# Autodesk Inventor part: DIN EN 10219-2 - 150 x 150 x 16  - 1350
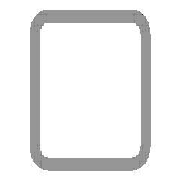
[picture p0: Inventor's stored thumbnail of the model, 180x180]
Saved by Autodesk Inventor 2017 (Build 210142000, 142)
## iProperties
_CCFamilyMember: 76
_CCFamilyDisplayName: DIN EN 10219-2 (Square Hollow Section - Cold Formed) - Cold formed welded structural hollow sections of non-alloy and fine grain structural steel
_FrameMemberDoc: Frame Member File
_Version: 15.0.0
_GetPNFromCC: 1
Created: 2017-11
Part Number: DIN EN 10219-2 - 150 x 150 x 16  - 1350
Material: Steel, Mild
Description: Cold formed welded structural hollow sections of non-alloy and fine grain structural steel
Document SubType Name: Modeling
Standard: DIN
Designer: iusti
Standard Revision: 2006-07
Standards Organization: DIN
Language: en-US
Size Designation: 150 x 150 x 16
Categories: <MemberInstance><Categories><Category DisplayName="Structural Shapes" InternalName="089c4875-fa83-4c05-b084-43b9cc11f5ed" Mnemonic="GRDR"><CategoryParameter Dis
Stock Number: 150 x 150 x 16
Mass: 79240 g
Surface Area: 12767.4 cm^2
Volume: 10094.3 cm^3
Density: 7.85 g/cm^3
Appearance: Semi-Polished
IsCustomPart: 1
G_L: 1350.000 mm
G_W: 150.000 mm
G_H: 150.000 mm
+25324788-8590-4B72-A89D-365C3D99059D+CUTDETAIL1: Cut
+F0281C93-BF98-4FCA-A581-8417B7D640E2+CUTDETAIL2: Cut
Author: iusti
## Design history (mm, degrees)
node "Start plane"
node "End plane"
sketch "Sketch"
  geometry: L1 (-75, -27)-(-75, 27); L2 (-27, 75)-(27, 75); L3 (75, 27)-(75, -27); L4 (27, -75)-(-27, -75); L5 (-27, 59)-(27, 59); L6 (59, 27)-(59, -27); L7 (27, -59)-(-27, -59); L8 (-59, -27)-(-59, 27); L9 (0, 118.918)-(0, -118.918) reference; L10 (-118.918, 0)-(118.918, 0) reference; A1 r 48 centre (-27, -27) between (-75, -27) and (-27, -75); A2 r 48 centre (-27, 27) between (-27, 75) and (-75, 27); A3 r 48 centre (27, 27) between (75, 27) and (27, 75); A4 r 48 centre (27, -27) between (27, -75) and (75, -27); A5 r 32 centre (-27, 27) between (-27, 59) and (-59, 27); A6 r 32 centre (27, 27) between (59, 27) and (27, 59); A7 r 32 centre (27, -27) between (27, -59) and (59, -27); A8 r 32 centre (-27, -27) between (-59, -27) and (-27, -59)
  constraints: 16 end point, 16 point on circle, 8 centre point, 8 tangent, 4 parallel, 3 equal radius, 2 perpendicular, 7 other
  dimensions: "d7" = 48 radius of A1 (= G_IR); "d10" = 150 distance between parallel lines of L2 L4 (= G_H); "d11" = 150 distance between parallel lines of L1 L3 (= G_W); "d12" = 16 distance between parallel lines of L3 L6 (= G_T); "d15" = 75 distance between parallel lines of L2 L10 (= 0.5 x d10); "d16" = 75 distance between parallel lines of L9 L3 (= 0.5 x d11)
extrude "Body" new body sketch "Sketch" stored distance "d3" = 1350 (= G_L); taper "d4" = 0 deg
node "Driven Length"
  sketch "Sketch3"
    geometry: L1 (0, 0)-(10, 0) reference
    constraints: 2 end point, 1 horizontal
  workplane "Work Plane3"
  sketch "Sketch4"
    geometry: L1 (-2, 75)-(12, 75) reference; L2 (-2, 1425)-(12, 1425) reference
    dimensions: "d18" = 1350 distance between parallel lines of L1 L2 (derived)
workplane "Work Plane4"
split "Split1"
workplane "Work Plane5"
split "Split2"
body "Solid1"
other parameters: "G_W" = 150 [user parameter; used in 1 equation term], "G_H" = 150 [user parameter; used in 1 equation term], "G_T" = 16 [user parameter; used in 1 equation term], "G_IR" = 48 [user parameter; used in 1 equation term], "G_L" = 1350 (= d18) [user parameter; used in 1 equation term], "G_OFFSET_START" = -75 [user parameter; used in 1 equation term], "G_OFFSET_END" = -75 [user parameter; used in 1 equation term], "d13" = 75 (= -G_OFFSET_START), "d14" = 1425 (= G_OFFSET_END + B_L), "d17" = 90 deg
